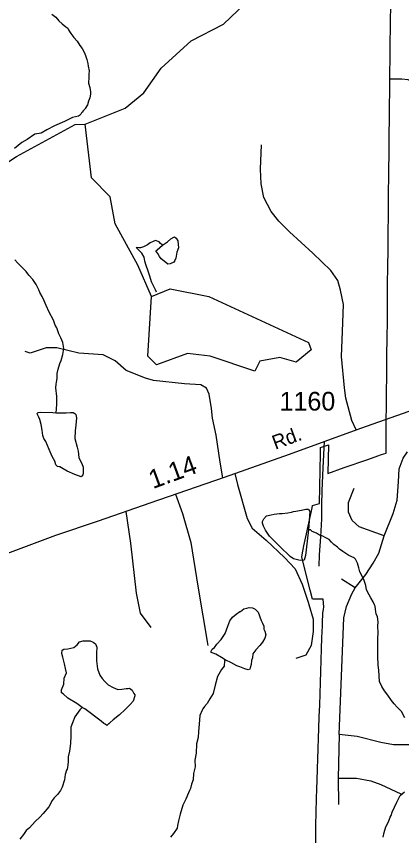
# Model space of a CAD drawing. Extents: x 2001466 to 2224147, y 644118 to 847247.
# Drawn here: x 2023901 to 2026475, y 717383 to 722853 of the extents above; entities that cross this region are included whole.
import ezdxf

# ---------------------------------------------------------------- set-up
doc = ezdxf.new("R2010")
doc.units = 0
for name, color, linetype in [('Exist Boundary Political City Limit New', 7, 'Continuous'), ('Exist Hydrographic Creek Single Shore', 7, 'Continuous'), ('Exist Hydrographic Misc Water Feature', 7, 'Continuous'), ('Exist Road Non-System Type 51', 7, 'Continuous'), ('Exist Road Secondary Mileage Hundredths English Label', 7, 'Continuous'), ('Exist Road Secondary Type 51 Attributed', 7, 'Continuous'), ('Exist Road Secondary Type 51 Label', 7, 'Continuous'), ('Exist Road Secondary Type 51 Number Label', 7, 'Continuous'), ('Map Preparation Boundary City Limit Buffer Line', 7, 'Continuous')]:
    doc.layers.add(name, color=color, linetype=linetype)

msp = doc.modelspace()

# ---------------------------------------------------------------- linework, layer by layer
at = {"layer": 'Exist Boundary Political City Limit New'}
for points in [[(2026316.6, 719918.4), (2026341.4, 719927.1), (2026357, 719932.5), (2026370.5, 719937.2), (2026371, 720000), (2026371.4, 720033.1), (2026372.2, 720114.4), (2026372.2, 720116.8), (2026372.4, 720130.3), (2026372.5, 720193.9), (2026372.8, 720211.8), (2026372.9, 720229), (2026374.1, 720331.6), (2026375.5, 720463.6), (2026377, 720619.2), (2026377.6, 720676.2), (2026379.4, 720849.8), (2026380.1, 720926.1), (2026380.5, 720956.7), (2026381.1, 721021.5), (2026381.6, 721060.8), (2026383, 721186.1), (2026384.1, 721290.6), (2026385.4, 721408.3), (2026386.8, 721527.1), (2026386.9, 721540.4), (2026388.2, 721670.3), (2026389.5, 721790.3), (2026390.4, 721869.8), (2026390.6, 721894.9), (2026391.6, 721992.9), (2026392.5, 722074.9), (2026393.4, 722156.9), (2026394.4, 722249.9), (2026395.6, 722359.9), (2026396.1, 722407.9), (2026396.6, 722457.8), (2026398, 722587.8), (2026398.6, 722642.8), (2026400.5, 722812.8), (2026401.8, 722932.2)], [(2025896.2, 716909.1), (2025902.5, 717451.2), (2025907, 717628.9), (2025908.8, 717694.2), (2025910.1, 717751), (2025912.9, 717828.2), (2025915.1, 717894.9), (2025917.4, 717959.7), (2025919.9, 718034.6), (2025922, 718095), (2025924.9, 718178.8), (2025927.5, 718253.8), (2025930, 718329.1), (2025932.6, 718404.1), (2025935.1, 718479.2), (2025937.8, 718554.3), (2025940.4, 718629.4), (2025942.9, 718704.5), (2025945.6, 718782.7), (2025946.1, 718800.8), (2025948.5, 718869.6), (2025952.9, 718893.6), (2025956, 718909.8), (2025951.5, 718960.8), (2025889.5, 718962.4), (2025879.4, 718962.7), (2025863.9, 719022.8), (2025807.8, 719241.6), (2025811.1, 719258.7), (2025822.5, 719317.7), (2025839.4, 719398.6), (2025876.8, 719571.3), (2025880.1, 719587), (2025926.2, 719601.4), (2025932.4, 719934), (2025933.1, 719974.5), (2025985.4, 719992.5), (2025981.1, 719801.7), (2026091.1, 719840), (2026249.9, 719895.2), (2026316.6, 719918.4)]]:
    msp.add_lwpolyline(points, dxfattribs=at)
at = {"layer": 'Exist Hydrographic Creek Single Shore'}
for points in [[(2024361.1, 722134.1), (2024628.1, 722240.2), (2024753.2, 722342.7), (2024869.2, 722507.7), (2025069.2, 722690.6), (2025286.1, 722801), (2025569.3, 723074.1)], [(2022184.2, 721048.6), (2022387.1, 721065.4), (2022704.1, 721173.8), (2023095.1, 721392.1), (2023903.2, 721917.1), (2024294.3, 722132.2), (2024361.1, 722134.1)]]:
    msp.add_lwpolyline(points, dxfattribs=at)
at = {"layer": 'Exist Hydrographic Misc Water Feature'}
for p, q in [((2024327.9, 722196.3), (2024324, 722192.3)), ((2024332, 722200.3), (2024327.9, 722196.3))]:
    msp.add_line(p, q, dxfattribs=at)
for points in [[(2024137.6, 722868.1), (2024165.5, 722848.1), (2024185.6, 722824.1), (2024207.5, 722804.1), (2024231.5, 722784.2), (2024245.7, 722774.2), (2024249.6, 722764.2), (2024255.7, 722752.2), (2024265.6, 722738.2), (2024285.6, 722712.2), (2024307.8, 722688.2), (2024325.6, 722658.2), (2024339.8, 722638.2), (2024353.7, 722614.3), (2024363.8, 722592.3), (2024371.8, 722566.2), (2024379.8, 722538.3), (2024381.8, 722520.3), (2024387.8, 722490.3), (2024385.7, 722466.3), (2024385.7, 722434.2), (2024383.9, 722420.3), (2024383.9, 722406.3), (2024391.9, 722378.3), (2024395.8, 722350.3), (2024395.8, 722334.3), (2024391.9, 722308.3), (2024383.9, 722286.3), (2024375.9, 722262.3), (2024361.9, 722238.3), (2024358, 722234.3), (2024353.9, 722228.3), (2024348, 722222.3), (2024341.8, 722214.3), (2024335.9, 722208.3), (2024332, 722200.3)], [(2024324, 722192.3), (2024316, 722186.3), (2024276, 722178.3), (2024221.9, 722152.2), (2024155.9, 722122.2), (2024104, 722096.2), (2024066, 722074.1), (2024024, 722066.1), (2023974, 722032.1), (2023938.1, 722010.1), (2023888.1, 721972)], [(2024803.2, 720983.3), (2024712.2, 721191.9), (2024561.2, 721467.2), (2024528.2, 721648.4), (2024403.1, 721775.6), (2024361.1, 722134.1)], [(2024878.3, 721324.7), (2024874.4, 721326.7), (2024864.3, 721336.7), (2024856.3, 721346.7), (2024830.3, 721356.7), (2024814.3, 721350.7), (2024796.2, 721340.7), (2024776.3, 721328.6), (2024750.5, 721314.6), (2024730.4, 721308.6), (2024720.4, 721308.6), (2024700.5, 721310.6)], [(2024878.3, 721324.7), (2024910.2, 721348.7), (2024934.2, 721366.8), (2024954.3, 721378.8), (2024958.2, 721380.8), (2024968.3, 721372.8), (2024980.4, 721354.8), (2024984.3, 721306.8), (2024972.4, 721278.8), (2024966.4, 721238.8), (2024960.5, 721222.8), (2024952.5, 721212.8), (2024928.5, 721200.7), (2024912.5, 721198.7), (2024888.5, 721218.8), (2024868.4, 721234.8), (2024858.4, 721250.8), (2024846.5, 721268.8), (2024832.3, 721286.7), (2024842.4, 721294.7), (2024878.3, 721324.7)], [(2024836.4, 721012.7), (2024830.5, 721026.7), (2024804.4, 721080.7), (2024792.3, 721118.7), (2024782.5, 721152.7), (2024768.3, 721188.7), (2024760.3, 721218.7), (2024754.4, 721244.6), (2024738.4, 721272.6), (2024722.4, 721290.6), (2024700.5, 721310.6)], [(2024165.1, 720206.4), (2024169, 720224.4), (2024171, 720272.4), (2024171, 720314.4), (2024164.9, 720372.4), (2024166.9, 720396.4), (2024169, 720410.4), (2024174.9, 720434.4), (2024174.9, 720468.4), (2024180.9, 720496.4), (2024190.9, 720534.4), (2024201, 720556.4), (2024210.8, 720594.4), (2024218.8, 720636.4), (2024210.8, 720676.4), (2024198.7, 720706.3), (2024184.8, 720732.4), (2024178.8, 720752.4), (2024172.7, 720772.4), (2024160.6, 720790.4), (2024148.7, 720824.4), (2024120.6, 720878.4), (2024100.7, 720922.3), (2024086.7, 720954.3), (2024072.6, 720982.3), (2024058.7, 721010.3), (2024052.5, 721026.2), (2024034.5, 721062.2), (2024010.5, 721096.3), (2023984.4, 721126.2), (2023966.6, 721150.2), (2023940.5, 721176.2), (2023910.6, 721206.2), (2023890.5, 721228.2)], [(2024803.2, 720983.3), (2024928.1, 721033.3), (2025187.1, 720982), (2025853.1, 720676.5), (2025870.1, 720626.9), (2025770.2, 720543.6), (2025662.2, 720575.3), (2025528.1, 720551.8), (2025495, 720483.6), (2025195.1, 720584.9), (2025045.2, 720601.1), (2024837, 720526.6), (2024779.2, 720583.5), (2024803.2, 720983.3)], [(2024165.1, 720206.4), (2024235, 720206.5), (2024263.1, 720208.5), (2024280.9, 720208.5), (2024291, 720202.5), (2024299, 720194.5), (2024303.1, 720172.5), (2024299.2, 720122.6), (2024295.1, 720086.5), (2024293, 720034.5), (2024307.2, 719976.6), (2024315.2, 719950.5), (2024319.1, 719908.5), (2024327.3, 719886.6), (2024339.2, 719866.6), (2024347.2, 719842.6), (2024347.2, 719820.6), (2024347.2, 719802.6), (2024345.3, 719792.6), (2024333.2, 719778.6), (2024291.2, 719794.5), (2024241.2, 719816.5), (2024213.3, 719832.6), (2024191.3, 719844.5), (2024187.2, 719844.5), (2024177.2, 719848.5), (2024165.3, 719858.5), (2024157.3, 719882.5), (2024141.3, 719914.4), (2024121.2, 719960.4), (2024097.2, 720014.4), (2024085.1, 720034.4), (2024079.2, 720054.4), (2024073.2, 720090.4), (2024067.1, 720128.4), (2024059.1, 720160.3), (2024051.1, 720176.3), (2024041, 720198.4), (2024041, 720202.4), (2024047, 720208.4), (2024060.9, 720210.4), (2024145, 720208.4), (2024165.1, 720206.4)], [(2025853.3, 719425.6), (2025851.2, 719407.5), (2025833.4, 719253.6), (2025827.4, 719237.6), (2025823.3, 719221.6), (2025797.3, 719219.5), (2025753.4, 719231.5), (2025729.4, 719247.5), (2025661.3, 719313.4), (2025593.3, 719383.4), (2025565.2, 719423.4), (2025551.2, 719449.4), (2025545.3, 719469.4), (2025545.3, 719479.3), (2025555.1, 719497.3), (2025573.2, 719517.3), (2025603.3, 719525.4), (2025623.2, 719529.4), (2025659.3, 719533.4), (2025677.1, 719533.4), (2025715.3, 719537.4), (2025739.3, 719543.4), (2025753.2, 719547.4), (2025769, 719549.5), (2025805.3, 719555.5), (2025835, 719561.5), (2025845.1, 719561.5), (2025853.3, 719561.5), (2025861.1, 719547.5), (2025853.3, 719425.6)], [(2026495.7, 718170.1), (2026473.8, 718212), (2026445.9, 718240.1), (2026425.8, 718262), (2026407.7, 718286), (2026381.7, 718320), (2026359.8, 718349.9), (2026341.7, 718377.9), (2026327.8, 718412), (2026321.6, 718487.9), (2026317.7, 718521.9), (2026315.7, 718582), (2026315.7, 718603.9), (2026315.7, 718627.9), (2026315.7, 718649.9), (2026315.7, 718671.9), (2026315.7, 718697.9), (2026317.5, 718735.9), (2026315.7, 718781.9), (2026317.5, 718809.9), (2026313.4, 718843.9), (2026305.4, 718863.9), (2026303.4, 718877.9), (2026299.5, 718893.9), (2026297.4, 718913.8), (2026293.5, 718923.8), (2026285.5, 718943.9), (2026269.5, 718969.8), (2026257.4, 718989.8), (2026241.2, 719023.8), (2026235.3, 719053.8), (2026225.2, 719085.8), (2026211.3, 719115.8), (2026195.3, 719143.7), (2026189.4, 719171.8), (2026179.3, 719201.8), (2026167.4, 719227.8), (2026157.4, 719237.8), (2026123.1, 719253.7), (2026081.3, 719279.7), (2026059.1, 719295.7), (2026047.3, 719309.7), (2026021.2, 719327.6), (2026007.3, 719341.6), (2025991.3, 719359.6), (2025965.2, 719373.7), (2025949.2, 719381.6), (2025925.2, 719389.6), (2025905.2, 719401.6), (2025877.3, 719413.5), (2025865.2, 719423.5), (2025853.3, 719425.6)], [(2025295.7, 718557.3), (2025271.7, 718571.3), (2025233.8, 718593.3), (2025215.8, 718601.2), (2025201.8, 718605.2), (2025201.8, 718615.2), (2025209.6, 718627.3), (2025223.8, 718639.3), (2025239.8, 718661.3), (2025269.7, 718693.3), (2025295.7, 718733.3), (2025313.6, 718781.3), (2025327.5, 718817.3), (2025345.6, 718841.3), (2025369.6, 718861.3), (2025393.5, 718879.3), (2025397.6, 718879.3), (2025421.6, 718897.4), (2025441.5, 718901.4), (2025455.7, 718905.4), (2025477.6, 718903.4), (2025495.7, 718895.4), (2025515.6, 718875.4), (2025537.5, 718819.5), (2025545.5, 718801.5), (2025553.5, 718781.4), (2025555.5, 718761.4), (2025561.7, 718747.4), (2025567.6, 718723.4), (2025561.7, 718701.5), (2025545.7, 718673.5), (2025527.7, 718651.4), (2025501.6, 718623.4), (2025481.7, 718597.4), (2025479.7, 718569.4), (2025471.7, 718551.5), (2025469.8, 718525.5), (2025463.9, 718503.4), (2025461.8, 718493.4), (2025449.7, 718489.4), (2025427.8, 718497.4), (2025393.8, 718509.4), (2025373.9, 718517.4), (2025333.9, 718539.4), (2025305.8, 718551.3), (2025295.7, 718557.3)], [(2024342, 718238.8), (2024306.2, 718264.8), (2024246.1, 718300.7), (2024214.1, 718328.7), (2024202, 718336.7), (2024202, 718356.7), (2024218, 718394.7), (2024220, 718434.7), (2024236, 718470.7), (2024229.9, 718498.7), (2024221.9, 718530.7), (2024212, 718574.7), (2024205.9, 718598.7), (2024207.7, 718620.7), (2024217.8, 718626.7), (2024245.9, 718630.7), (2024265.8, 718634.8), (2024285.9, 718638.7), (2024307.8, 718656.8), (2024323.8, 718676.7), (2024347.8, 718682.7), (2024379.8, 718682.7), (2024393.9, 718682.7), (2024413.8, 718674.8), (2024429.8, 718662.8), (2024439.8, 718640.8), (2024435.7, 718600.8), (2024436, 718548.8), (2024443.9, 718496.8), (2024457.9, 718454.8), (2024473.9, 718432.9), (2024491.9, 718410.8), (2024513.9, 718388.9), (2024547.9, 718370.9), (2024579.9, 718358.9), (2024605.9, 718360.9), (2024621.9, 718363), (2024635.9, 718364.9), (2024648, 718365), (2024656, 718367), (2024674, 718353), (2024685.9, 718331), (2024691.9, 718323), (2024691.9, 718315), (2024682, 718281), (2024662.1, 718259), (2024628.1, 718225), (2024590.2, 718189), (2024548.1, 718154.9), (2024528, 718136.9), (2024520, 718128.9), (2024516.1, 718128.9), (2024506.1, 718119), (2024494, 718126.9), (2024486, 718130.9), (2024468.1, 718146.9), (2024358, 718228.8), (2024342, 718238.8)], [(2025295.7, 718557.3), (2025291.8, 718549.3), (2025289.8, 718515.3), (2025271.7, 718491.3), (2025243.9, 718445.3), (2025229.9, 718387.3), (2025216, 718331.3), (2025194, 718295.3), (2025176, 718265.3), (2025157.9, 718245.3), (2025147.9, 718229.3), (2025141.9, 718221.3), (2025126, 718185.2), (2025122.1, 718127.3), (2025118, 718077.3), (2025116.1, 718037.3), (2025104.2, 717995.3), (2025102.2, 717933.3), (2025094.2, 717887.3), (2025096.2, 717841.3), (2025084.1, 717797.3), (2025082.3, 717755.3), (2025072.2, 717725.3), (2025064.2, 717697.3), (2025058.3, 717683.3), (2025052.3, 717667.3), (2025034.3, 717625.3), (2025012.4, 717585.3), (2024994.5, 717525.3), (2024984.5, 717481.2), (2024978.3, 717451.2), (2024974.4, 717433.3), (2024950.4, 717397.3), (2024930.3, 717371.2)], [(2024342, 718238.8), (2024326, 718222.8), (2024292, 718176.8), (2024276.2, 718134.7), (2024264.1, 718106.7), (2024264.1, 718048.8), (2024262.3, 717996.8), (2024256.3, 717946.8), (2024248.3, 717908.8), (2024248.3, 717874.8), (2024244.2, 717854.8), (2024242.4, 717836.8), (2024240.3, 717826.8), (2024236.2, 717820.8), (2024228.2, 717790.8), (2024222.3, 717754.8), (2024208.3, 717706.8), (2024196.5, 717684.8), (2024176.4, 717656.8), (2024154.4, 717634.8), (2024140.5, 717616.7), (2024118.3, 717574.7), (2024080.6, 717530.7), (2024058.5, 717506.7), (2024026.5, 717476.7), (2023988.5, 717434.7), (2023966.6, 717416.6), (2023948.5, 717390.7), (2023924.8, 717358.7)], [(2026352.4, 717372.1), (2026358.3, 717404.1), (2026370.2, 717442.1), (2026386.2, 717474.2), (2026396.3, 717500.2), (2026398.1, 717506.2), (2026404.2, 717516.1), (2026412.2, 717540.1), (2026442.2, 717606.2), (2026464.1, 717650.2), (2026494.1, 717676.1)]]:
    msp.add_lwpolyline(points, dxfattribs=at)
at = {"layer": 'Exist Road Non-System Type 51'}
msp.add_line((2025833.9, 718587.8), (2025767.5, 718564.8), dxfattribs=at)
for points in [[(2026619.5, 722352.6), (2026562.3, 722405.1), (2026519.3, 722429), (2026476.4, 722433.8), (2026397.7, 722433.8)], [(2026170.4, 720092.8), (2026142.8, 720155.4), (2026103, 720304.7), (2026092.6, 720372.7), (2026073.4, 720582.5), (2026079.3, 720749.5), (2026086.7, 720928.3), (2026067.5, 721024.3), (2026048.3, 721089.3), (2026002.5, 721157.3), (2025881.5, 721271.8), (2025726.4, 721413.7), (2025654, 721486.1), (2025603.8, 721551.1), (2025555.1, 721644.2), (2025537.4, 721734.3), (2025531.5, 721833.3), (2025538.9, 721994.4)], [(2025280.7, 719772.3), (2025262.2, 719875.7), (2025235.6, 720055.8), (2025211.1, 720170.3), (2025205, 720233.8), (2025188.6, 720329.9), (2025172.3, 720370.8), (2025133.4, 720393.3), (2025025.1, 720399.5), (2024816.5, 720422), (2024763.4, 720436.3), (2024634.6, 720487.5), (2024561, 720552.9), (2024481.2, 720593.8), (2024319.7, 720604.1), (2024172.5, 720638.9), (2024100.9, 720638.9), (2023992.8, 720605.1), (2023960.3, 720615.9)], [(2025956.9, 720014.6), (2025949.5, 719838), (2025941.8, 719684.5), (2025940.2, 719590)], [(2026359.2, 719384.2), (2026418.5, 719534.2), (2026444.4, 719623.1), (2026453.6, 719745.5), (2026459.2, 719832.5), (2026485.1, 719902.5), (2026514.7, 719945.1)], [(2025361.8, 719800.9), (2025378.5, 719727.7), (2025443.4, 719500.4), (2025475.9, 719435.4), (2025570.9, 719356.1), (2025692.3, 719240.6), (2025762.6, 719164.8), (2025811.3, 719061.9), (2025850, 718941)], [(2024965.3, 719663.5), (2025011.8, 719534.6), (2025065.9, 719339.7), (2025114.6, 719047.4), (2025179.6, 718652.3)], [(2026359.2, 719384.2), (2026190.8, 719445.3), (2026144.6, 719487.9), (2026120.5, 719541.6), (2026120.5, 719608.2), (2026157.5, 719702.7)], [(2024632.9, 719547.9), (2024664.2, 719336.4), (2024702.4, 719001.1), (2024728.2, 718867.2), (2024799.5, 718773.5)], [(2025940.2, 719590), (2025940.2, 719497), (2025932.5, 719378), (2025923.2, 719258.7), (2025921.6, 719181.2)], [(2026164.9, 719036.4), (2026235.2, 719127.1), (2026285.2, 719203), (2026322.2, 719269.7), (2026359.2, 719384.2)], [(2026164.9, 719036.4), (2026072.4, 719095.6)], [(2026057.6, 718058.7), (2026089, 718838), (2026107.5, 718912.1), (2026142.7, 718997.5), (2026164.9, 719036.4)], [(2025850, 718941), (2025854.6, 718926.6), (2025882.9, 718827.4), (2025882.9, 718746.6), (2025871.4, 718651.4), (2025833.9, 718587.8)], [(2026057.6, 718058.7), (2026052, 717766.1)], [(2026784.7, 718006.9), (2026621.8, 717992.1), (2026523.8, 717988.4), (2026420.1, 717988.4), (2026336.8, 718005), (2026177.9, 718043.9), (2026057.6, 718058.7)], [(2026052, 717766.1), (2026172.3, 717766.1), (2026268.6, 717749.5), (2026335.2, 717723.5), (2026470.3, 717662.4)], [(2026052, 717766.1), (2026053.9, 717590.2)]]:
    msp.add_lwpolyline(points, dxfattribs=at)
at = {"layer": 'Exist Road Secondary Type 51 Attributed'}
msp.add_lwpolyline([(2022233.4, 719484.1), (2022515.8, 719389.9), (2022788.6, 719308.5), (2023075.4, 719241.4), (2023262.9, 719202.3), (2023416.5, 719181.6), (2023506.6, 719175.2), (2023611.9, 719187.2), (2023735.6, 719227.9), (2024165.5, 719388.3), (2024451.1, 719484.1), (2024794.5, 719604.7), (2025292.3, 719776.3), (2025726.7, 719930.4), (2026202.1, 720104.4), (2026683.6, 720273.6), (2027102.4, 720414.1), (2027319.4, 720449.2), (2027551.1, 720460.4), (2027676.7, 720468.4), (2027738.2, 720488.4), (2027823.5, 720547.4), (2027925.6, 720637.6)], dxfattribs=at)
at = {"layer": 'Map Preparation Boundary City Limit Buffer Line'}
for points in [[(2026316.6, 719918.4), (2026341.4, 719927.1), (2026357, 719932.5), (2026370.5, 719937.2), (2026371, 720000), (2026371.4, 720033.1), (2026372.2, 720114.4), (2026372.2, 720116.8), (2026372.4, 720130.3), (2026372.5, 720193.9), (2026372.8, 720211.8), (2026372.9, 720229), (2026374.1, 720331.6), (2026375.5, 720463.6), (2026377, 720619.2), (2026377.6, 720676.2), (2026379.4, 720849.8), (2026380.1, 720926.1), (2026380.5, 720956.7), (2026381.1, 721021.5), (2026381.6, 721060.8), (2026383, 721186.1), (2026384.1, 721290.6), (2026385.4, 721408.3), (2026386.8, 721527.1), (2026386.9, 721540.4), (2026388.2, 721670.3), (2026389.5, 721790.3), (2026390.4, 721869.8), (2026390.6, 721894.9), (2026391.6, 721992.9), (2026392.5, 722074.9), (2026393.4, 722156.9), (2026394.4, 722249.9), (2026395.6, 722359.9), (2026396.1, 722407.9), (2026396.6, 722457.8), (2026398, 722587.8), (2026398.6, 722642.8), (2026400.5, 722812.8), (2026401.8, 722932.2)], [(2025896.2, 716909.1), (2025902.5, 717451.2), (2025907, 717628.9), (2025908.8, 717694.2), (2025910.1, 717751), (2025912.9, 717828.2), (2025915.1, 717894.9), (2025917.4, 717959.7), (2025919.9, 718034.6), (2025922, 718095), (2025924.9, 718178.8), (2025927.5, 718253.8), (2025930, 718329.1), (2025932.6, 718404.1), (2025935.1, 718479.2), (2025937.8, 718554.3), (2025940.4, 718629.4), (2025942.9, 718704.5), (2025945.6, 718782.7), (2025946.1, 718800.8), (2025948.5, 718869.6), (2025952.9, 718893.6), (2025956, 718909.8), (2025951.5, 718960.8), (2025889.5, 718962.4), (2025879.4, 718962.7), (2025863.9, 719022.8), (2025807.8, 719241.6), (2025811.1, 719258.7), (2025822.5, 719317.7), (2025839.4, 719398.6), (2025876.8, 719571.3), (2025880.1, 719587), (2025926.2, 719601.4), (2025932.4, 719934), (2025933.1, 719974.5), (2025985.4, 719992.5), (2025981.1, 719801.7), (2026091.1, 719840), (2026249.9, 719895.2), (2026316.6, 719918.4)]]:
    msp.add_lwpolyline(points, dxfattribs=at)

# ---------------------------------------------------------------- texts
at = {"layer": 'Exist Road Secondary Mileage Hundredths English Label'}
msp.add_text('1.14', height=125, rotation=20.1102, dxfattribs=at).set_placement((2024813.5, 719696.5))
at = {"layer": 'Exist Road Secondary Type 51 Label'}
msp.add_text('Rd.', height=95, rotation=20.3085, dxfattribs=at).set_placement((2025631, 719958.8))
at = {"layer": 'Exist Road Secondary Type 51 Number Label'}
msp.add_text('1160', height=125, dxfattribs=at).set_placement((2025659.6, 720221))

doc.saveas('drawing.dxf')
